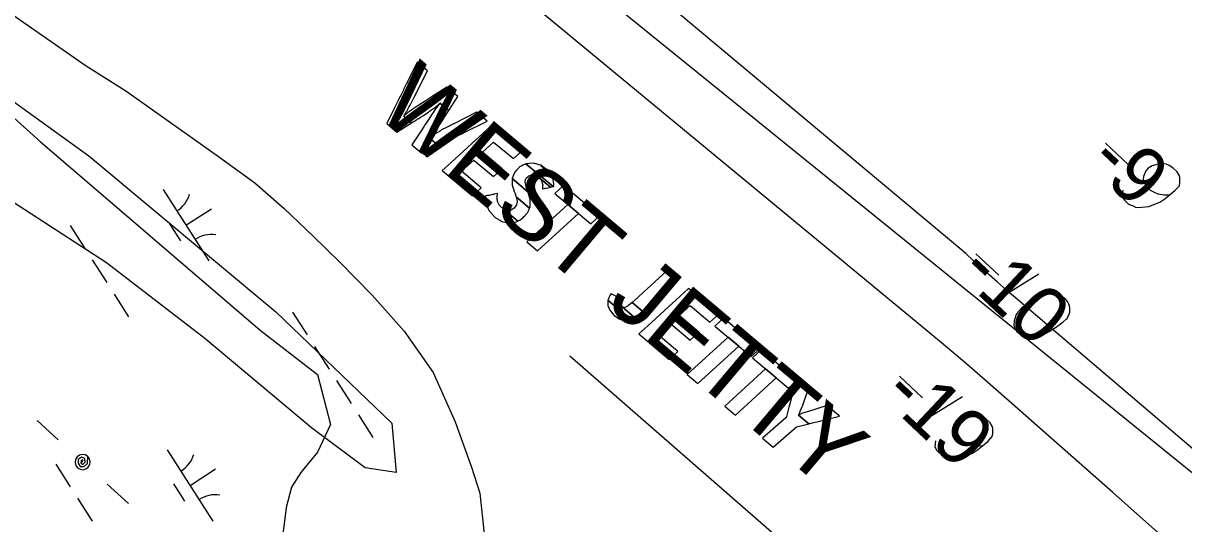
# Model space of a CAD drawing. Extents: x 3962991 to 3983549, y 181631 to 204078.
# Drawn here: x 3979195 to 3979881, y 188086 to 188382 of the extents above; entities that cross this region are included whole.
import ezdxf

# ---------------------------------------------------------------- set-up
doc = ezdxf.new("R2010")
doc.units = 0
for name, color, linetype in [('V-ANNO-MASK', 7, 'Continuous'), ('V-ANNO-MASK2', 7, 'Continuous'), ('V-GRID-MAJR', 7, 'Continuous'), ('V-RIVR-EDGE', 7, 'Continuous'), ('V-RIVR-IDEN', 7, 'Continuous'), ('V-RIVR-RANG', 7, 'Continuous'), ('V-RRAP-FSHR', 7, 'Continuous'), ('V-SITE-VEGE', 7, 'Continuous'), ('V-TOPO-DPTH', 7, 'Continuous'), ('V-TOPO-MINR', 7, 'Continuous'), ('V-UTIL-LINE', 7, 'Continuous'), ('V-WETL-SWMP', 7, 'Continuous')]:
    doc.layers.add(name, color=color, linetype=linetype)

msp = doc.modelspace()

# ---------------------------------------------------------------- linework, layer by layer
at = {"layer": 'V-ANNO-MASK2'}
for p, q in [((3979834.79, 188310.9), (3979848.26, 188298.27)), ((3979834.79, 188310.9), (3979848.26, 188298.27)), ((3979758.23, 188245.66), (3979771.7, 188233.03)), ((3979758.23, 188245.66), (3979771.7, 188233.03)), ((3979795.39, 188233.6), (3979765.93, 188215.3)), ((3979795.39, 188233.6), (3979765.93, 188215.3)), ((3979713.11, 188173.25), (3979726.55, 188160.59)), ((3979713.11, 188173.25), (3979726.55, 188160.59)), ((3979750.23, 188161.11), (3979720.73, 188142.87)), ((3979750.23, 188161.11), (3979720.73, 188142.87))]:
    msp.add_line(p, q, dxfattribs=at)
for points in [[(3979414.43, 188331.52), (3979409.99, 188322.49), (3979415.99, 188317.44), (3979424.61, 188322.94), (3979419.95, 188326.86), (3979421.72, 188329.63), (3979421.96, 188330.08), (3979422.19, 188330.52), (3979422.28, 188330.67), (3979422.28, 188330.68), (3979423.08, 188332.15), (3979423.75, 188333.47), (3979424.11, 188334.16), (3979424.11, 188334.17), (3979425.54, 188336.95), (3979425.91, 188337.68), (3979425.91, 188337.69), (3979427.5, 188340.79), (3979427.57, 188340.93), (3979427.57, 188340.93), (3979434.07, 188353.62), (3979427.88, 188358.85), (3979421.56, 188346), (3979421.49, 188345.86), (3979419.94, 188342.72), (3979419.58, 188341.98), (3979418.19, 188339.16), (3979418.19, 188339.15), (3979417.84, 188338.44), (3979417.19, 188337.12), (3979416.44, 188335.6), (3979416.36, 188335.43), (3979416.14, 188334.98), (3979415.91, 188334.53)], [(3979422.48, 188328.99), (3979419.95, 188326.86), (3979424.61, 188322.94), (3979427.49, 188324.77), (3979427.49, 188324.77), (3979427.93, 188325.05), (3979428.36, 188325.32), (3979428.52, 188325.42), (3979428.51, 188325.42), (3979429.96, 188326.35), (3979431.24, 188327.15), (3979431.91, 188327.59), (3979431.92, 188327.59), (3979434.61, 188329.3), (3979435.29, 188329.78), (3979438.17, 188331.79), (3979438.29, 188331.9), (3979441.38, 188334.58), (3979446.55, 188330.22), (3979451.88, 188338.61), (3979445.5, 188343.99), (3979436.81, 188338.44), (3979433.23, 188336.16), (3979433.1, 188336.07), (3979430.1, 188334.16), (3979429.39, 188333.7), (3979426.7, 188331.99), (3979426.7, 188331.98), (3979426.04, 188331.53), (3979424.81, 188330.69), (3979423.4, 188329.73), (3979423.25, 188329.63), (3979422.87, 188329.31)], [(3979430.21, 188318.21), (3979424.82, 188309.99), (3979430.71, 188305.03), (3979440.29, 188309.71), (3979435.43, 188313.81), (3979437.51, 188316.32), (3979437.83, 188316.7), (3979438.11, 188317.1), (3979438.1, 188317.1), (3979438.21, 188317.25), (3979439.13, 188318.62), (3979439.94, 188319.81), (3979440.35, 188320.47), (3979440.36, 188320.48), (3979442.01, 188323.07), (3979442.44, 188323.75), (3979444.28, 188326.64), (3979444.36, 188326.77), (3979444.36, 188326.78), (3979446.55, 188330.22), (3979441.38, 188334.58), (3979438.9, 188331.38), (3979438.81, 188331.26), (3979436.91, 188328.41), (3979436.46, 188327.74), (3979434.78, 188325.18), (3979434.77, 188325.17), (3979434.35, 188324.52), (3979433.56, 188323.31), (3979432.65, 188321.93), (3979432.56, 188321.78), (3979432.29, 188321.37), (3979432.01, 188320.96)], [(3979438.04, 188315.88), (3979435.43, 188313.81), (3979440.29, 188309.71), (3979443.49, 188311.28), (3979443.98, 188311.52), (3979444.46, 188311.75), (3979444.63, 188311.83), (3979446.24, 188312.62), (3979447.66, 188313.31), (3979448.41, 188313.68), (3979448.42, 188313.68), (3979448.41, 188313.69), (3979451.41, 188315.14), (3979451.4, 188315.15), (3979452.19, 188315.53), (3979455.53, 188317.16), (3979455.68, 188317.23), (3979455.68, 188317.24), (3979469.33, 188323.91), (3979462.94, 188329.3), (3979449.52, 188322.43), (3979449.37, 188322.35), (3979446.1, 188320.67), (3979445.32, 188320.27), (3979442.39, 188318.77), (3979442.38, 188318.76), (3979441.7, 188318.34), (3979440.42, 188317.53), (3979438.96, 188316.61), (3979438.82, 188316.5), (3979438.43, 188316.19)], [(3979447.95, 188299.58), (3979442.78, 188294.85), (3979460.64, 188279.79), (3979465.82, 188284.52), (3979454.18, 188294.33), (3979461.49, 188301), (3979473.13, 188291.19), (3979478.18, 188295.8), (3979466.54, 188305.61), (3979473.14, 188311.62), (3979484.78, 188301.81), (3979489.95, 188306.52), (3979472.08, 188321.58), (3979466.91, 188316.87), (3979460.32, 188310.86), (3979455.26, 188306.25)], [(3979484.66, 188291.63), (3979484.03, 188290.06), (3979493.4, 188282.16), (3979492.29, 188285.19), (3979491.72, 188288.19), (3979491.86, 188288.62), (3979492.41, 188290.25), (3979493.38, 188291.15), (3979494, 188291.72), (3979494.57, 188291.88), (3979494.56, 188291.88), (3979495.11, 188292.03), (3979496.02, 188292.28), (3979497.37, 188292.05), (3979498.04, 188291.93), (3979500.13, 188290.56), (3979506.75, 188284.97), (3979508.25, 188285.29), (3979492.21, 188298.81), (3979491.02, 188298.23), (3979490.73, 188298.09), (3979490.39, 188297.93), (3979489.71, 188297.6), (3979488.95, 188297.23), (3979488.49, 188297.01), (3979488.15, 188296.66), (3979487.57, 188296.04), (3979486.68, 188295.09), (3979485.58, 188293.91), (3979485.41, 188293.51)], [(3979492.69, 188298.85), (3979492.22, 188298.81), (3979508.25, 188285.29), (3979508.68, 188285.38), (3979508.71, 188286.86), (3979508.35, 188289.27), (3979508.3, 188289.4), (3979507.2, 188292.13), (3979505.86, 188293.81), (3979501.05, 188297.87), (3979500.03, 188298.18), (3979496.64, 188299.22), (3979496.55, 188299.21), (3979494.31, 188299)], [(3979504.76, 188295.19), (3979501.06, 188297.86), (3979505.85, 188293.82)], [(3979485.78, 188281.1), (3979486.51, 188279.2), (3979494.37, 188272.57), (3979494.77, 188273.52), (3979494.76, 188274.49), (3979494.75, 188277.23), (3979494.75, 188277.23), (3979494.75, 188277.68), (3979493.53, 188281.82), (3979493.4, 188282.16), (3979484.02, 188290.06), (3979484.03, 188289.83), (3979484.1, 188286.65), (3979484.11, 188286.19), (3979485.23, 188282.52)], [(3979502.04, 188284.95), (3979501.93, 188283.94), (3979502.96, 188284.17), (3979503.56, 188284.3), (3979504.15, 188284.42), (3979505.11, 188284.62), (3979505.96, 188284.8), (3979506.39, 188284.89), (3979506.75, 188284.97), (3979500.13, 188290.56), (3979500.81, 188289.6), (3979501.61, 188288.47), (3979501.87, 188287.36), (3979502.16, 188286.1), (3979502.09, 188285.53)], [(3979470.81, 188270.51), (3979474.09, 188267.13), (3979476.72, 188265.52), (3979476.72, 188265.53), (3979478, 188264.74), (3979481.27, 188263.95), (3979482.25, 188263.71), (3979484.75, 188264.11), (3979486.58, 188264.41), (3979486.68, 188264.42), (3979487.42, 188264.86), (3979478.6, 188272.3), (3979476.69, 188274.19), (3979476.07, 188275.38), (3979475.48, 188276.51), (3979475.29, 188278.27), (3979475.21, 188278.98), (3979475.24, 188279.34), (3979475.4, 188281.02), (3979475.41, 188281.16), (3979475.26, 188281.13), (3979473.53, 188280.78), (3979473.16, 188280.71), (3979472.55, 188280.58), (3979471.02, 188280.27), (3979470.42, 188280.14), (3979469.78, 188280.02), (3979469.51, 188279.96), (3979468.5, 188279.75), (3979468.4, 188279.73), (3979468.4, 188277.9), (3979468.87, 188274.99), (3979468.99, 188274.31), (3979470.57, 188271.01)], [(3979514.36, 188285.95), (3979509.22, 188281.28), (3979530.55, 188263.3), (3979535.69, 188267.97)], [(3979479.32, 188271.97), (3979478.6, 188272.3), (3979487.42, 188264.86), (3979487.62, 188264.98), (3979488.08, 188265.25), (3979488.53, 188265.51), (3979489.64, 188266.17), (3979490.09, 188266.44), (3979490.36, 188266.59), (3979491.27, 188267.64), (3979492.76, 188269.33), (3979493.21, 188269.85), (3979493.71, 188271.04), (3979494.37, 188272.57), (3979486.5, 188279.2), (3979487.06, 188276.65), (3979486.8, 188275.26), (3979486.66, 188274.48), (3979485.34, 188272.64), (3979484.12, 188271.85), (3979483.86, 188271.69), (3979483.43, 188271.4), (3979481.71, 188271.26), (3979481.03, 188271.2)], [(3979517.01, 188274.71), (3979492.84, 188252.65), (3979499.14, 188247.34), (3979523.31, 188269.4)], [(3979558.31, 188219.76), (3979555.01, 188216.75), (3979561.27, 188211.47), (3979564.59, 188214.46), (3979565.19, 188215.02), (3979582, 188230.35), (3979575.71, 188235.65), (3979558.92, 188220.31)], [(3979540.97, 188218.94), (3979540.65, 188218.16), (3979554.33, 188206.63), (3979555.29, 188206.87), (3979556.65, 188207.82), (3979556.69, 188207.84), (3979548.91, 188214.4), (3979548.46, 188215.39), (3979548.28, 188215.81), (3979548.64, 188217.04), (3979548.66, 188217.14), (3979549.14, 188217.86), (3979549.26, 188218.03), (3979549.42, 188218.27), (3979548.06, 188219.04), (3979547.11, 188219.58), (3979543.08, 188221.84), (3979542.66, 188222.08), (3979542, 188221.11), (3979541.88, 188220.94), (3979541.62, 188220.54), (3979541.59, 188220.52)], [(3979564.19, 188203.02), (3979559.01, 188198.29), (3979576.88, 188183.23), (3979582.06, 188187.95), (3979570.42, 188197.76), (3979577.73, 188204.44), (3979589.37, 188194.63), (3979594.42, 188199.24), (3979582.78, 188209.05), (3979589.38, 188215.06), (3979601.02, 188205.25), (3979606.19, 188209.96), (3979588.32, 188225.02), (3979583.15, 188220.31), (3979576.56, 188214.3), (3979571.5, 188209.69)], [(3979542.76, 188211.11), (3979544.44, 188209.21), (3979547.78, 188206.88), (3979548.26, 188206.76), (3979551.53, 188205.92), (3979551.64, 188205.95), (3979554.33, 188206.63), (3979540.66, 188218.16), (3979540.61, 188215.25), (3979540.69, 188215.05), (3979541.78, 188212.22)], [(3979550.46, 188213.7), (3979548.91, 188214.4), (3979556.69, 188207.84), (3979557.09, 188208.12), (3979557.26, 188208.24), (3979558.25, 188208.93), (3979558.33, 188208.99), (3979559.06, 188209.5), (3979559.24, 188209.62), (3979561.27, 188211.47), (3979555.01, 188216.75), (3979552.9, 188214.96), (3979552.74, 188214.83), (3979551.89, 188214.41), (3979551.81, 188214.37), (3979550.66, 188213.81)], [(3979609.09, 188207.52), (3979603.95, 188202.84), (3979625.28, 188184.86), (3979630.42, 188189.54)], [(3979611.74, 188196.27), (3979587.57, 188174.22), (3979593.87, 188168.91), (3979618.04, 188190.97)], [(3979631.27, 188188.81), (3979626.14, 188184.14), (3979647.47, 188166.16), (3979652.6, 188170.83)], [(3979633.93, 188177.57), (3979609.76, 188155.51), (3979616.06, 188150.21), (3979640.23, 188172.26)], [(3979645.95, 188148.6), (3979632.14, 188136.65), (3979638.45, 188131.33), (3979652.24, 188143.29), (3979652.28, 188143.32), (3979659.44, 188145.13), (3979653.31, 188150.3), (3979654.11, 188151.84), (3979654.15, 188151.97), (3979655.57, 188155.35), (3979655.63, 188155.53), (3979659.04, 188165.41), (3979652.07, 188171.29), (3979649.26, 188160.9), (3979649.21, 188160.71), (3979648.21, 188156.98), (3979648.17, 188156.85), (3979647.68, 188155.04), (3979645.96, 188148.65)], [(3979654.98, 188151.1), (3979653.31, 188150.3), (3979659.44, 188145.13), (3979661.46, 188145.64), (3979661.61, 188145.68), (3979665.79, 188146.74), (3979666, 188146.79), (3979677.64, 188149.73), (3979670.23, 188155.98), (3979659.22, 188152.5), (3979659.02, 188152.44), (3979655.11, 188151.16)]]:
    msp.add_lwpolyline(points, close=True, dxfattribs=at)
for points in [[(3979845.01, 188283.24), (3979844.56, 188279.68), (3979845.75, 188277.47), (3979848.45, 188274.95), (3979851.09, 188273.91), (3979852.61, 188273.22), (3979854.11, 188272.89), (3979860.44, 188273.47), (3979866.89, 188276.1), (3979869.81, 188278.06), (3979875.81, 188282.92), (3979878.52, 188285.81), (3979878.83, 188287.69), (3979878.73, 188290.67), (3979878.52, 188291.59), (3979877.13, 188293.98), (3979874.63, 188296.32), (3979872.35, 188297.74), (3979870.64, 188298.62), (3979867.27, 188298.88), (3979862.46, 188297.61), (3979860.08, 188296.23), (3979858.64, 188294.69), (3979857.25, 188291.28), (3979857.12, 188289.6), (3979857.75, 188287.57), (3979859.51, 188284.82), (3979861.25, 188283.2), (3979863.9, 188281.79), (3979865.79, 188281.11), (3979869.54, 188280.48), (3979871.6, 188280.36), (3979872.72, 188280.4)], [(3979845.01, 188283.24), (3979844.56, 188279.68), (3979845.75, 188277.47), (3979848.45, 188274.95), (3979851.09, 188273.91), (3979852.61, 188273.22), (3979854.11, 188272.89), (3979860.44, 188273.47), (3979866.89, 188276.1), (3979869.81, 188278.06), (3979875.81, 188282.92), (3979878.52, 188285.81), (3979878.83, 188287.69), (3979878.73, 188290.67), (3979878.52, 188291.59), (3979877.13, 188293.98), (3979874.63, 188296.32), (3979872.35, 188297.74), (3979870.64, 188298.62), (3979867.27, 188298.88), (3979862.46, 188297.61), (3979860.08, 188296.23), (3979858.64, 188294.69), (3979857.25, 188291.28), (3979857.12, 188289.6), (3979857.75, 188287.57), (3979859.51, 188284.82), (3979861.25, 188283.2), (3979863.9, 188281.79), (3979865.79, 188281.11), (3979869.54, 188280.48), (3979871.6, 188280.36), (3979872.72, 188280.4)], [(3979811.55, 188218.45), (3979811.17, 188218.81), (3979809.83, 188219.7), (3979808.88, 188220.23), (3979808.12, 188220.58), (3979806.8, 188221.1), (3979805.1, 188221.6), (3979803.6, 188221.93), (3979801.92, 188222.06), (3979800.62, 188221.83), (3979799.14, 188221.41), (3979797.66, 188220.99), (3979796, 188220.37), (3979794.89, 188219.97), (3979793.43, 188219.17), (3979791.04, 188217.79), (3979787.76, 188215.44), (3979785.21, 188213.5), (3979783.23, 188211.38), (3979781.98, 188209.66), (3979781.12, 188207.2), (3979780.8, 188205.7), (3979780.68, 188203.64), (3979781.11, 188201.79), (3979781.51, 188201.06), (3979782.48, 188199.78), (3979783.44, 188198.88), (3979785.16, 188197.63), (3979786.87, 188196.75), (3979788.37, 188196.43), (3979790.62, 188196.13), (3979791.74, 188196.16), (3979793.23, 188196.21), (3979794.53, 188196.44), (3979795.46, 188196.66), (3979796.75, 188197.26), (3979797.3, 188197.46), (3979798.59, 188198.06), (3979800.05, 188198.86), (3979801.52, 188199.65), (3979802.43, 188200.24), (3979803.17, 188200.64), (3979804.08, 188201.23), (3979806.09, 188202.6), (3979807.19, 188203.38), (3979808.28, 188204.16), (3979809.74, 188205.33), (3979811.55, 188206.88), (3979812.09, 188207.46), (3979812.62, 188208.41), (3979813.15, 188209.36), (3979813.66, 188211.05), (3979813.8, 188212.36), (3979813.76, 188213.48), (3979813.54, 188214.78), (3979813.13, 188215.89), (3979812.73, 188216.62), (3979812.33, 188217.36), (3979811.55, 188218.45)], [(3979811.55, 188218.45), (3979811.17, 188218.81), (3979809.83, 188219.7), (3979808.88, 188220.23), (3979808.12, 188220.58), (3979806.8, 188221.1), (3979805.1, 188221.6), (3979803.6, 188221.93), (3979801.92, 188222.06), (3979800.62, 188221.83), (3979799.14, 188221.41), (3979797.66, 188220.99), (3979796, 188220.37), (3979794.89, 188219.97), (3979793.43, 188219.17), (3979791.04, 188217.79), (3979787.76, 188215.44), (3979785.21, 188213.5), (3979783.23, 188211.38), (3979781.98, 188209.66), (3979781.12, 188207.2), (3979780.8, 188205.7), (3979780.68, 188203.64), (3979781.11, 188201.79), (3979781.51, 188201.06), (3979782.48, 188199.78), (3979783.44, 188198.88), (3979785.16, 188197.63), (3979786.87, 188196.75), (3979788.37, 188196.43), (3979790.62, 188196.13), (3979791.74, 188196.16), (3979793.23, 188196.21), (3979794.53, 188196.44), (3979795.46, 188196.66), (3979796.75, 188197.26), (3979797.3, 188197.46), (3979798.59, 188198.06), (3979800.05, 188198.86), (3979801.52, 188199.65), (3979802.43, 188200.24), (3979803.17, 188200.64), (3979804.08, 188201.23), (3979806.09, 188202.6), (3979807.19, 188203.38), (3979808.28, 188204.16), (3979809.74, 188205.33), (3979811.55, 188206.88), (3979812.09, 188207.46), (3979812.62, 188208.41), (3979813.15, 188209.36), (3979813.66, 188211.05), (3979813.8, 188212.36), (3979813.76, 188213.48), (3979813.54, 188214.78), (3979813.13, 188215.89), (3979812.73, 188216.62), (3979812.33, 188217.36), (3979811.55, 188218.45)], [(3979734.4, 188135.07), (3979733.94, 188131.51), (3979735.13, 188129.31), (3979737.82, 188126.77), (3979740.46, 188125.73), (3979741.97, 188125.03), (3979743.48, 188124.7), (3979749.8, 188125.27), (3979756.26, 188127.88), (3979759.19, 188129.84), (3979765.2, 188134.68), (3979767.91, 188137.56), (3979768.23, 188139.44), (3979768.14, 188142.42), (3979767.93, 188143.35), (3979766.55, 188145.73), (3979764.05, 188148.08), (3979761.77, 188149.51), (3979760.07, 188150.39), (3979756.7, 188150.66), (3979751.88, 188149.4), (3979749.5, 188148.02), (3979748.05, 188146.49), (3979746.66, 188143.09), (3979746.52, 188141.4), (3979747.14, 188139.37), (3979748.91, 188136.62), (3979750.63, 188134.99), (3979753.29, 188133.58), (3979755.18, 188132.89), (3979758.93, 188132.26), (3979760.98, 188132.13), (3979762.1, 188132.16)], [(3979734.4, 188135.07), (3979733.94, 188131.51), (3979735.13, 188129.31), (3979737.82, 188126.77), (3979740.46, 188125.73), (3979741.97, 188125.03), (3979743.48, 188124.7), (3979749.8, 188125.27), (3979756.26, 188127.88), (3979759.19, 188129.84), (3979765.2, 188134.68), (3979767.91, 188137.56), (3979768.23, 188139.44), (3979768.14, 188142.42), (3979767.93, 188143.35), (3979766.55, 188145.73), (3979764.05, 188148.08), (3979761.77, 188149.51), (3979760.07, 188150.39), (3979756.7, 188150.66), (3979751.88, 188149.4), (3979749.5, 188148.02), (3979748.05, 188146.49), (3979746.66, 188143.09), (3979746.52, 188141.4), (3979747.14, 188139.37), (3979748.91, 188136.62), (3979750.63, 188134.99), (3979753.29, 188133.58), (3979755.18, 188132.89), (3979758.93, 188132.26), (3979760.98, 188132.13), (3979762.1, 188132.16)]]:
    msp.add_lwpolyline(points, dxfattribs=at)
at = {"layer": 'V-GRID-MAJR'}
msp.add_spline([(3971886.05, 188358.46), (3973487.19, 188388.71), (3978814.65, 188489.84), (3982563.08, 188561.47)], degree=3, dxfattribs=at)
at = {"layer": 'V-RIVR-EDGE'}
msp.add_lwpolyline([(3979185.49, 188329.41), (3979205.15, 188311.93), (3979335.12, 188200.53), (3979368.98, 188174.32), (3979376.62, 188144.83), (3979368.98, 188128.45), (3979359.15, 188116.44), (3979353.69, 188107.7), (3979350.41, 188095.69), (3979348.23, 188078.21)], dxfattribs=at)
at = {"layer": 'V-RRAP-FSHR'}
msp.add_lwpolyline([(3979518.12, 188185.25), (3979726.95, 188003.16), (3979771.52, 187930.58)], dxfattribs=at)
at = {"layer": 'V-SITE-VEGE'}
msp.add_lwpolyline([(3979149.57, 188364.18), (3979233.85, 188303.57), (3979344.47, 188211.33), (3979412.95, 188145.45), (3979415.59, 188116.46), (3979397.15, 188119.09), (3979365.55, 188142.81), (3979302.33, 188195.52), (3979244.39, 188240.32), (3979162.74, 188293.02)], dxfattribs=at)
at = {"layer": 'V-TOPO-DPTH'}
for points in [[(3977515.59, 190129.47), (3978679.07, 189092.54), (3980218.42, 187847.46)], [(3980218.42, 187847.46), (3980186.53, 187874.69), (3979782.72, 188218.5), (3979779.15, 188221.57), (3979777.97, 188222.61), (3979770.89, 188228.85), (3979766.19, 188233.02), (3979761.5, 188237.21), (3979756.84, 188241.44), (3979752.19, 188245.68), (3979154.89, 188745.01), (3979105.65, 188777.43), (3979078.71, 188795.74), (3979052.13, 188814.58), (3979026.13, 188834.19), (3979000.51, 188854.31), (3978556.54, 189213.7)]]:
    msp.add_lwpolyline(points, dxfattribs=at)
at = {"layer": 'V-TOPO-MINR'}
for points in [[(3980218.42, 187847.46), (3980186.53, 187874.69), (3979782.72, 188218.5), (3979779.15, 188221.57), (3979777.97, 188222.61), (3979770.89, 188228.85), (3979766.19, 188233.02), (3979761.5, 188237.21), (3979756.84, 188241.44), (3979752.19, 188245.68), (3979154.89, 188745.01), (3979105.65, 188777.43), (3979078.71, 188795.74), (3979052.13, 188814.58), (3979026.13, 188834.19), (3979000.51, 188854.31), (3978556.54, 189213.7)], [(3980158.34, 187808.51), (3980006.31, 187952.05), (3979964.98, 187990.68), (3979923.39, 188029.01), (3979881.41, 188066.92), (3979839.18, 188104.55), (3979779.4, 188157.24), (3979766.8, 188168.24), (3979754.14, 188179.16), (3979741.37, 188189.96), (3979728.53, 188200.67), (3979422.77, 188453.31), (3979374.82, 188493.02), (3979326.94, 188532.82), (3979279.15, 188572.72), (3979231.43, 188612.7), (3979137.31, 188691.75)]]:
    msp.add_lwpolyline(points, dxfattribs=at)
at = {"layer": 'V-UTIL-LINE'}
for points in [[(3979203.23, 188147.05), (3979215.81, 188135.62)], [(3979230.2, 188122.53), (3979230.39, 188123.96), (3979229.36, 188123.42), (3979229.21, 188122.06), (3979230.4, 188121.2), (3979231.6, 188122.4), (3979231.55, 188124.75), (3979229.51, 188125.39), (3979227.46, 188124.09), (3979227.45, 188121.8), (3979228.74, 188119.98), (3979231.15, 188119.86), (3979233.12, 188121.79), (3979233.23, 188125.87), (3979231.73, 188126.77), (3979229.99, 188127.03), (3979228.28, 188126.6), (3979226.87, 188125.56), (3979225.97, 188124.06), (3979225.71, 188122.32), (3979226.13, 188120.61), (3979227.18, 188119.2), (3979228.68, 188118.3), (3979230.42, 188118.04), (3979232.12, 188118.46), (3979233.54, 188119.51), (3979234.44, 188121.01), (3979234.7, 188122.75), (3979234.27, 188124.45), (3979233.23, 188125.87)], [(3979244.68, 188109.4), (3979257.26, 188097.97)]]:
    msp.add_lwpolyline(points, dxfattribs=at)
at = {"layer": 'V-WETL-SWMP'}
for p, q in [((3979277.74, 188283.52), (3979304.72, 188241.43)), ((3979291.23, 188262.48), (3979306.38, 188272.19)), ((3979222.83, 188262.23), (3979231.47, 188248.76)), ((3979281.5, 188263.36), (3979287.97, 188253.26)), ((3979235.78, 188242.02), (3979244.42, 188228.55)), ((3979248.74, 188221.82), (3979257.37, 188208.35)), ((3979354.3, 188211.1), (3979362.94, 188197.63)), ((3979367.26, 188190.89), (3979375.89, 188177.42)), ((3979380.21, 188170.69), (3979388.85, 188157.22)), ((3979393.16, 188150.49), (3979401.8, 188137.02)), ((3979280.15, 188129.8), (3979307.14, 188087.71)), ((3979214.27, 188121.33), (3979222.91, 188107.86)), ((3979293.65, 188108.75), (3979308.8, 188118.47)), ((3979283.91, 188109.64), (3979290.39, 188099.54)), ((3979227.23, 188101.12), (3979235.86, 188087.65))]:
    msp.add_line(p, q, dxfattribs=at)
msp.add_lwpolyline([(3979174.53, 188396.8), (3979232.22, 188356.72), (3979255.73, 188341.93), (3979310.52, 188303.13), (3979331.94, 188287.54), (3979349.22, 188272.4), (3979366.48, 188256.02), (3979382.5, 188240.48), (3979401.39, 188221.17), (3979420.25, 188199.79), (3979437.43, 188175.52), (3979450.39, 188146.31), (3979460.06, 188119.63), (3979464.88, 188104.22), (3979467.52, 188080.11), (3979465.29, 188066.02), (3979459.31, 188050.72)], dxfattribs=at)
for centre, start, end in [((3979276.52, 188285.86), 301.89187, 343.43553), ((3979306.34, 188239.35), 81.89186, 123.43552), ((3979278.94, 188132.13), 301.89187, 343.43553), ((3979308.75, 188085.63), 81.89186, 123.43552)]:
    msp.add_arc(centre, 17.62, start, end, dxfattribs=at)

# ---------------------------------------------------------------- texts
at = {"layer": 'V-ANNO-MASK'}
for s, height, rotation, p in [('WEST', 42, 319.87152, (3979402.15, 188329.1)), ('-9', 33.5, 316.84717, (3979823.24, 188298.58)), ('JETTY', 42, 319.87152, (3979539.01, 188215.15)), ('-10', 33.5, 316.84717, (3979746.69, 188233.34)), ('-19', 33.5, 316.70833, (3979701.53, 188160.96))]:
    msp.add_text(s, height=height, rotation=rotation, dxfattribs=at).set_placement(p)
at = {"layer": 'V-RIVR-IDEN'}
for s, p in [('WEST', (3979402.15, 188329.1)), ('JETTY', (3979539.01, 188215.15))]:
    msp.add_text(s, height=42, rotation=319.87152, dxfattribs=at).set_placement(p)
at = {"layer": 'V-RIVR-RANG'}
for s, rotation, p in [('-9', 316.84717, (3979823.24, 188298.58)), ('-10', 316.84717, (3979746.69, 188233.34)), ('-19', 316.70833, (3979701.53, 188160.96))]:
    msp.add_text(s, height=33.5, rotation=rotation, dxfattribs=at).set_placement(p)

doc.saveas('drawing.dxf')
